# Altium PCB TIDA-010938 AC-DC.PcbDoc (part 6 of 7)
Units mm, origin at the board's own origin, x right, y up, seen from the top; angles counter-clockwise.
Board outline 275 x 170 mm, 4 copper layers (Top Layer, Layer 1, Layer 2, Bottom Layer), stack 1.787 mm thick; 711 components, 426 nets, 2196 pads, 1444 vias.
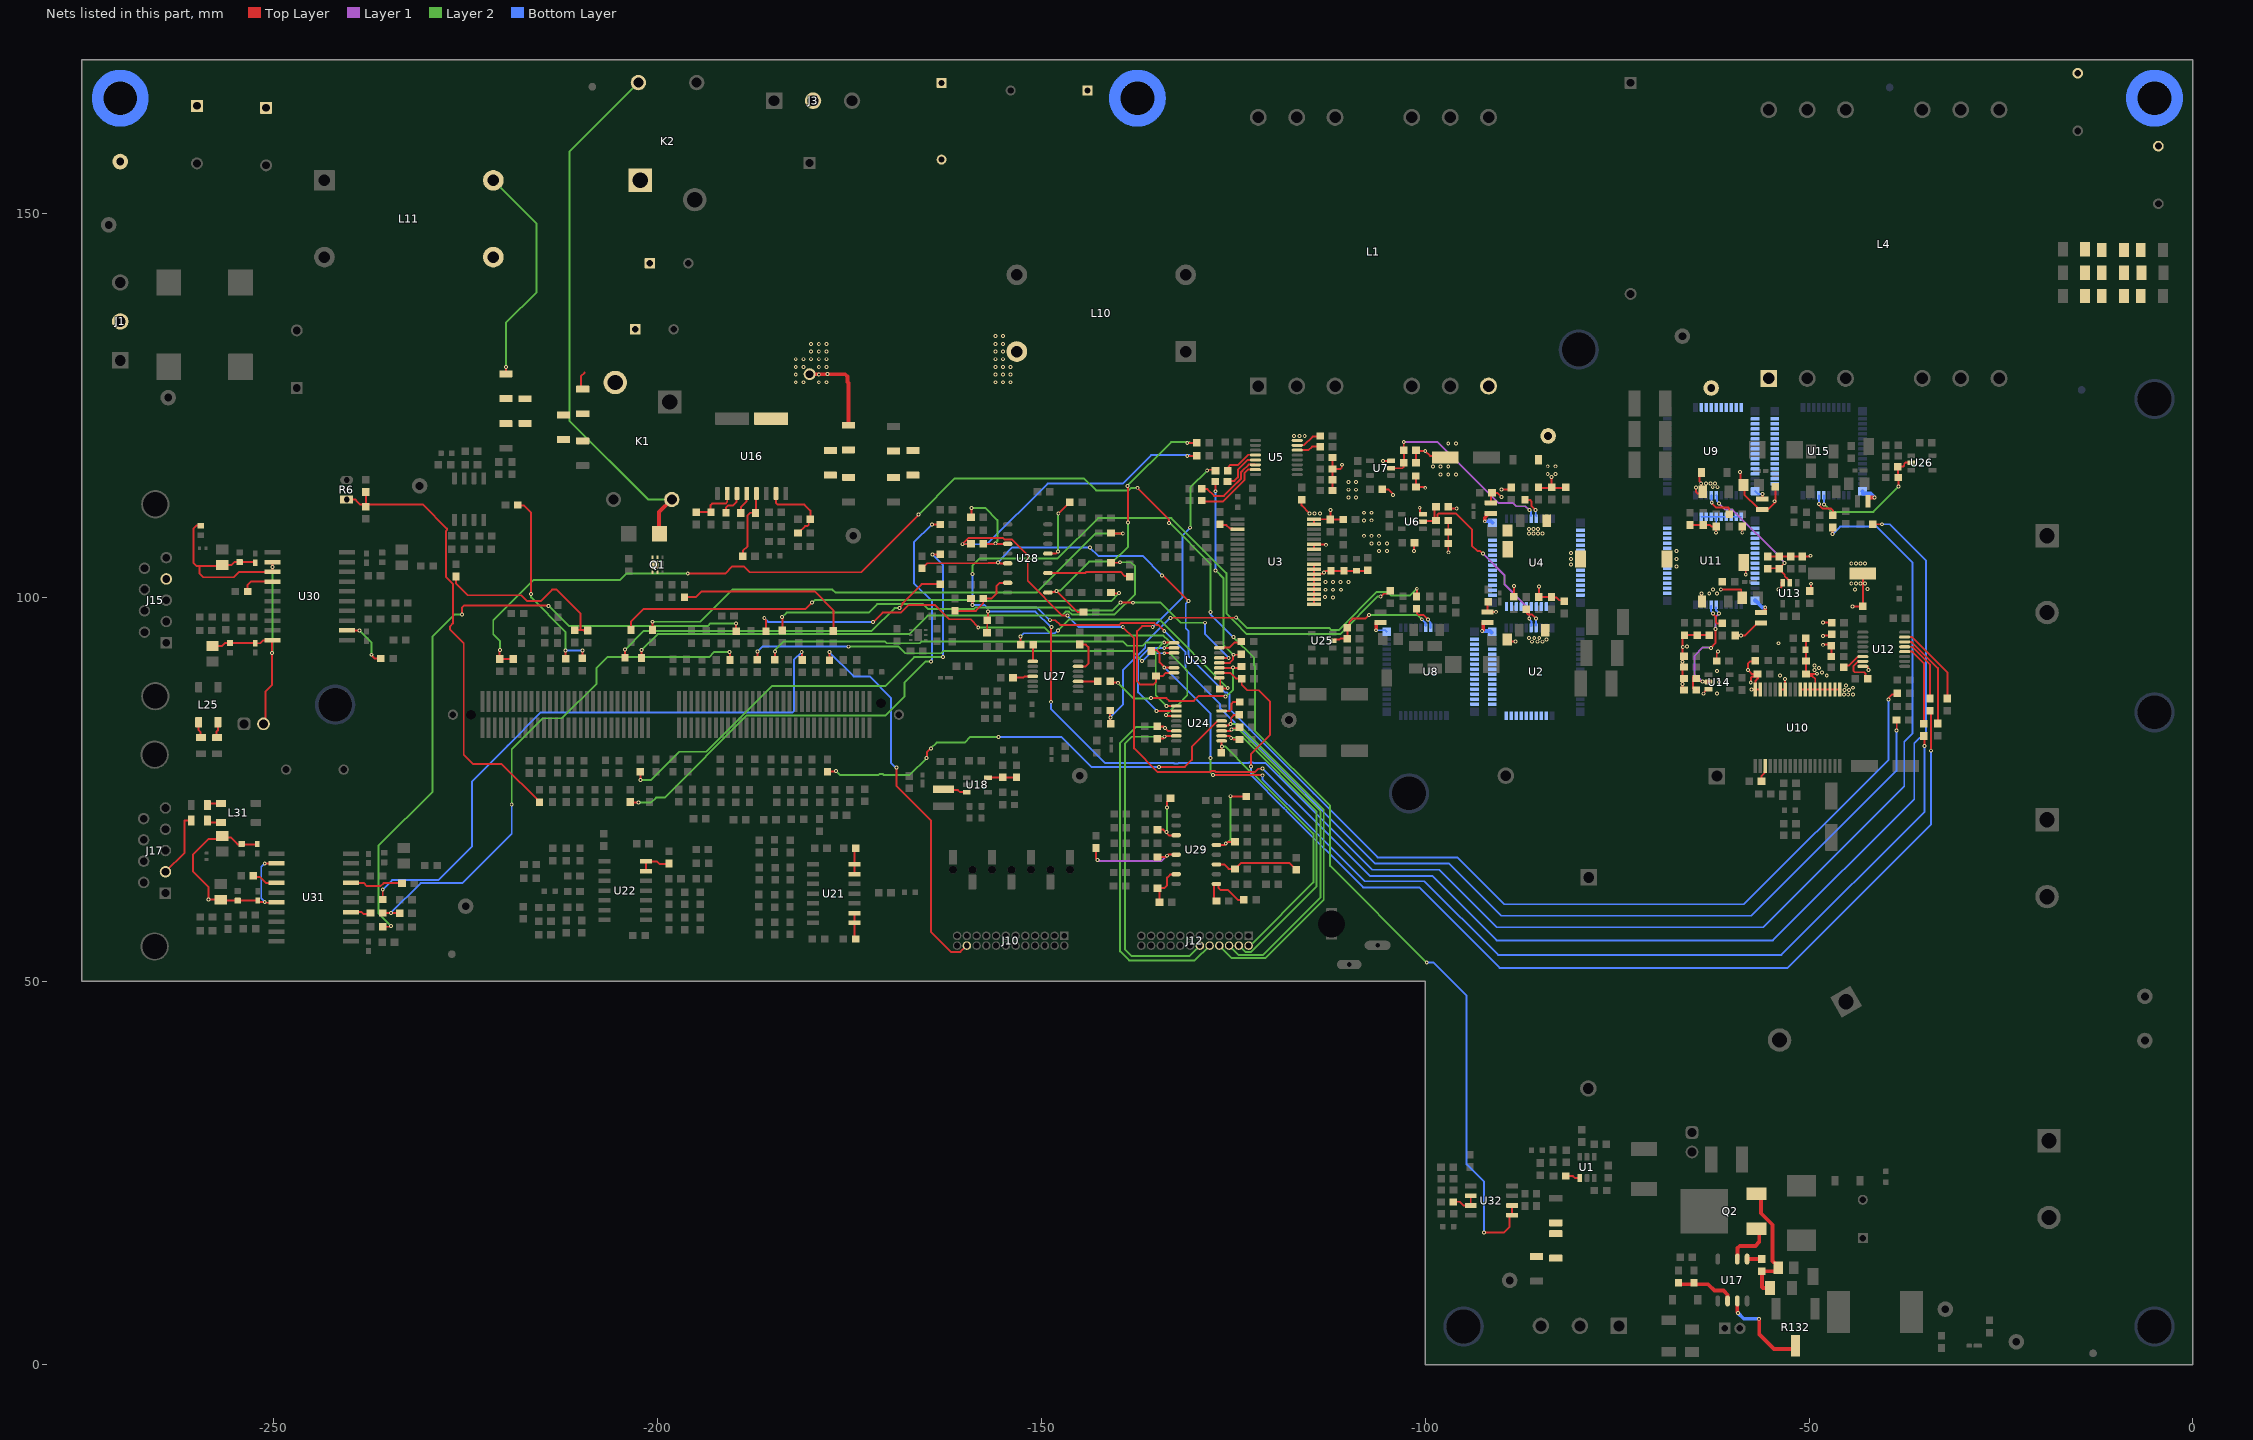
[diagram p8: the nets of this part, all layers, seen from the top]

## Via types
v1: diameter 0.508, hole 0.254, Top Layer to Bottom Layer, tented both sides, 1436 vias
v2: diameter 0.508, hole 0.254, Top Layer to Bottom Layer, 6 vias
v3: diameter 0.5, hole 0.2, Top Layer to Bottom Layer, 2 vias

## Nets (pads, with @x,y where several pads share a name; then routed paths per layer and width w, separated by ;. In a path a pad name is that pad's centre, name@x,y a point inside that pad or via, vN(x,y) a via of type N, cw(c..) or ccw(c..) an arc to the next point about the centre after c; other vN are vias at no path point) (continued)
NetJ17_2: J17.2 R321.2 | length 8.6
  Top Layer w0.25: J17.2@-264.105,64.23 -261.6,66.735 -261.6,70.9 R321.2@-260.75,70.9
NetL2_2: L2.2 U2.42 | length 3
  Top Layer w0.5: v1(-92.579,95.606) -92.579,95.608 -92.45,95.737 -92.45,96.65 -92.375,96.725 L2.2@-91.9,96.725
  Bottom Layer w0.5: v1(-92.579,95.606) -92.577,95.604 -91.571,95.604 U2.42@-91.375,95.408
NetL3_2: L3.2 U4.42 | length 2.7
  Top Layer w0.5: v1(-92.25,109.888) -92.248,109.89 -92.248,110.352 -92,110.6 -92,110.85 L3.2@-91.5,110.85
  Bottom Layer w0.5: v1(-92.25,109.888) -92.248,109.887 -91.412,109.887 U4.42@-91.225,109.7
NetL5_2: L5.2 U8.42 | length 3
  Top Layer w0.5: v1(-106.389,95.693) -106.389,95.696 -106.375,95.71 -106.375,96.65 -106.3,96.725 L5.2@-105.825,96.725
  Bottom Layer w0.25: v1(-106.389,95.693) -105.211,95.693 U8.42@-105.018,95.5
NetL6_2: L6.2 U9.42 | length 1.8
  Top Layer w0.25: L6.2@-56.1,112.775 -56.077,112.798 v1(-56.077,113.421)
  Bottom Layer w0.25: U9.42@-57.025,113.8 -56.648,113.423 -56.079,113.423 v1(-56.077,113.421)
NetL7_2: L7.2 U11.42 | length 2.9
  Top Layer w0.5: L7.2@-56.25,97.975 -55.784,97.975 -55.709,98.05 -55.709,98.645 v1(-55.708,98.646)
  Bottom Layer w0.5: U11.42@-57.025,99.55 -57,99.55 -56.098,98.648 v1(-55.708,98.646) v1(-55.708,98.646)
NetL9_2: L9.2 U15.42 | length 3
  Top Layer w0.5: L9.2@-42.325,112.5 -42.325,112.925 -42.25,113 v1(-41.5,113)
  Bottom Layer w0.5: U15.42@-43.025,113.8 U15.42@-43,113.8 ; U15.42@-43,113.5 -42,113.5 v1(-41.5,113)
NetL14_1: L14.1 U18.3 | length 2.9
  Top Layer w0.25: L14.1@-162.766,74.981 -162.66,74.875 -160.875,74.875 -160.599,74.599 -160.049,74.599 U18.3@-160,74.55
NetL25_3: L25.3 R316.1 | length 1.9
  Top Layer w0.25: L25.3@-259.775,83.725 -259.775,82.675 -259.525,82.425 R316.1@-259.525,81.95
NetL25_4: L25.4 R312.1 | length 1.9
  Top Layer w0.25: R312.1@-257.45,81.95 -257.475,81.975 -257.475,82.45 -257.275,82.65 L25.4@-257.275,83.725
NetL31_3: L31.3 R325.1 | length 1.9
  Top Layer w0.25: R325.1@-258.709,72.922 -258.507,73.125 -256.9,73.125 L31.3@-256.875,73.15
NetL31_4: L31.4 R321.1 | length 1.7
  Top Layer w0.25: R321.1@-258.65,70.9 -258.425,70.675 -257.125,70.675 L31.4@-257.1,70.7
NetQ2_1: Q2.1 U17.6 | length 5.9
  Top Layer w0.5: U17.6@-59.349,13.777 -59.33,13.796 -59.33,14.292 -59.303,14.319 -59.303,15.207 -59.01,15.5 -57,15.5 -56.5,16 -56.5,17.07 Q2.1@-56.35,17.22
NetQ2_3: Q2.3 R96.2 R97.1 R98.1 | length 16.4
  Top Layer w0.5: Q2.3@-56.85,22.28 -56.8,22.28 -56.25,21.73 -56.25,19.758 -54.75,18.258 -54.75,13.95 -54.748,13.948 -54.748,13.548 -54.233,13.033 R97.1@-54.233,12.117 ; R98.1@-55.1,9.75 -55.35,10 -56,10 -56.15,10.15 R96.2@-56.15,12.2 R97.1@-54.316,12.2
NetR2_1: R2.1 U1.1 | length 1.9
  Top Layer w0.25: R2.1@-81.625,24.625 -81.6,24.6 -80.775,24.6 -80.518,24.343 U1.1@-79.883,24.343
NetR8_1: R8.1 U5.7 | length 3.3
  Top Layer w0.25: U5.7@-116.675,119.788 -115.812,119.788 -114.675,120.925 R8.1@-113.8,120.925
NetR9_1: R9.1 U5.6 | length 3.1
  Top Layer w0.25: U5.6@-116.675,119.153 -115.222,119.153 -114.75,119.625 -113.925,119.625 R9.1@-113.85,119.55
NetR11_2: R11.2 U3.3 | length 2.1
  Top Layer w0.25: R11.2@-126.725,109.5 -126.625,109.4 -125.9,109.4 -125.45,108.95 -125.125,108.95 U3.3@-124.925,108.75
NetR18_1: R18.1 U12.7 | length 4.7
  Top Layer w0.25: U12.7@-43.637,91.61 -44.2,91.047 -44.2,90.371 -44.054,90.225 -42.8,90.225 -42.654,90.079 -42.654,89.725 -42.579,89.65 R18.1@-42.075,89.65 ; U12.7@-43.562,91.635 -43.256,91.635 U12.7@-43,91.635 ; U12.7@-43.256,91.606 U12.7@-43.225,91.575
NetR19_1: R19.1 U12.6 | length 2.6
  Top Layer w0.25: R19.1@-45.5,90.875 -45.265,91.11 -44.771,91.11 U12.6@-43.657,92.225 ; U12.6@-43.582,92.25 U12.6@-43.375,92.25 ; U12.6@-43.18,92.27 U12.6@-43.175,92.275
NetR21_2: R21.2 R23.1
NetR23_2: R23.2 R36.1
NetR24_2: R24.2 U5.12 | length 4.1
  Top Layer w0.25: R24.2@-125.725,116.475 -125.65,116.55 -125.65,116.95 -125.375,117.225 -124.381,117.225 -123.056,118.55 U5.12@-122.75,118.55 ; R24.2@-125.55,116.5 R24.2@-125.525,116.475 ; U5.12@-122.154,118.489 U5.12@-122.125,118.518
NetR26_2: R26.2 U5.13 | length 5.2
  Top Layer w0.25: R26.2@-125.6,115.15 -124.85,115.15 -124.4,115.6 -124.4,116.59 -123.108,117.883 U5.13@-122.125,117.883
NetR28_2: R28.2 U5.14 | length 9.6
  Top Layer w0.25: R28.2@-129.1,114.125 -129.046,114.071 -128.371,114.071 -127.5,113.2 -126.234,113.2 -125.109,114.325 -124,115.434 -124,115.5 -123.975,115.525 -123.975,116.303 -123.828,116.45 -123.825,116.45 -123,117.275 -122.152,117.275 U5.14@-122.125,117.248
NetR31_2: R31.2 U5.15 | length 8.8
  Top Layer w0.25: R31.2@-128.7,112.475 -126.325,112.475 -123.567,115.233 -123.567,116.142 -123.097,116.613 U5.15@-122.125,116.613
NetR37_2: R37.2 U8.49 | length 3.5
  Top Layer w0.25: R37.2@-101.15,98.5 -101.05,98.4 -101.05,97.85 -100.854,97.654 -100.204,97.654 -99.734,97.184 -99.716,97.184 v1@-99.7,97.2
  Bottom Layer w0.25: v1@-99.575,97.05 -99.601,97.024 -99.601,96.981 -99.327,96.707 -99.327,96.019 U8.49@-99.308,96
  other v1: -99.65,97.1
NetR39_1: R39.1 U27.3 | length 2.7
  Top Layer w0.25: U27.3@-145.219,89.033 -142.558,89.033 R39.1@-142.5,88.975
NetR47_2: R47.2 U10.3 | length 1.7
  Top Layer w0.25: R47.2@-56.2,76.025 -56.2,76.69 -55.825,77.065 -55.825,77.275 U10.3@-55.65,77.45
NetR50_1: R50.1 U30.2 | length 6.9
  Top Layer w0.25: U30.2@-240.456,95.682 -240.45,95.676 -238.852,95.676 v1(-238.846,95.67) ; v1(-237.25,92.5) -237.25,92.43 -237.021,92.201 -237.021,92.158 -236.864,92 R50.1@-236.05,92
  Layer 2 w0.25: v1(-238.846,95.67) -237.25,94.074 v1(-237.25,92.5)
NetR58_2: R58.2 U12.12 | length 11.2
  Top Layer w0.25: U12.12@-37.55,92.905 -36.53,92.905 -35.05,91.425 -35.05,83.7 R58.2@-35.275,83.475
NetR61_2: R61.2 U12.13 | length 8.6
  Top Layer w0.25: U12.13@-37.55,93.54 -36.556,93.54 -34.25,91.234 R61.2@-34.25,86.85
NetR63_2: R63.2 U12.14 | length 12.5
  Top Layer w0.25: U12.14@-37.55,94.175 -37.521,94.146 -36.596,94.146 -33.225,90.775 R63.2@-33.225,84
NetR65_2: R65.2 U12.15 | length 10.7
  Top Layer w0.25: U12.15@-37.55,94.81 -36.56,94.81 -31.975,90.225 R65.2@-31.975,86.975
NetR68_1: R68.1 U27.6 | length 4.4
  Top Layer w0.25: R68.1@-145.014,93.829 -144.204,93.829 -143.875,93.5 -143.875,91.35 -144.25,90.975 U27.6@-144.65,90.975
NetR71_2: R71.2 U15.49 | length 4.2
  Top Layer w0.25: v1(-48.725,112.125) -48.725,112.055 -48.579,111.909 -48.579,111.881 -48.269,111.571 -47.146,111.571 -46.9,111.325 -46.9,110.725 R71.2@-46.725,110.55
  Bottom Layer w0.152: v1@-48.73,112.13 v1(-48.725,112.125)
  Bottom Layer w0.25: U15.49@-48.735,113.275 -48.73,113.27 v1@-48.73,112.195
NetR73_1: R73.1 U27.8 | length 2.2
  Top Layer w0.25: R73.1@-151.075,93.8 -151.119,93.756 -151.119,91.725 -151.094,91.7 U27.8@-151.05,91.7
NetR77_1: R77.1 R79.1 R80.1 R185.2 R235.2 R290.2
NetR83_1: R83.1 U16.6 | length 2.8
  Top Layer w0.25: R83.1@-189.15,111.025 -189.15,111.725 -188.4,112.475 -188.4,113.501 U16.6@-188.385,113.516
NetR84_2: R84.2 R88.1 U16.4 | length 6.1
  Top Layer w0.25: R84.2@-194.978,111.079 -193.304,111.079 R88.1@-193.125,110.9 ; R88.1@-193.1,111.225 -193.1,112 -192.9,112.2 -191.15,112.2 -190.925,112.425 U16.4@-190.925,113.516
NetR85_2: R85.2 R87.1 U16.7 | length 8.9
  Top Layer w0.25: R85.2@-188.875,105.625 -188.875,106.05 -188.275,106.65 -188.275,110.675 -187.95,111 -187.275,111 R87.1@-187.25,110.975 ; R87.1@-187.2,111.125 -187.2,113.431 U16.7@-187.115,113.516
NetR86_2: R86.2 U16.5 | length 3.1
  Top Layer w0.25: R86.2@-191.075,111.425 -191.075,111.709 -190.855,111.93 -190.22,111.93 -189.7,112.45 -189.7,113.471 U16.5@-189.655,113.516
NetR91_2: R91.2 R92.2 U16.9 | length 9.8
  Top Layer w0.25: U16.9@-184.575,113.516 -184.575,112.3 -184.325,112.05 -180.875,112.05 -180.1,111.275 ; R91.2@-181.696,108.373 -181.671,108.373 -180.794,109.25 -180.5,109.25 -180.303,109.447 -180.303,109.952 -180.1,110.155 -180.1,111.25
NetR93_1: R93.1 R95.2 U17.2 | length 7.8
  Top Layer w0.5: R93.1@-67,10.7 -66.8,10.5 -65,10.5 -63.169,10.5 -62.338,9.669 -61.167,9.669 -60.638,9.14 -60.638,8.346 U17.2@-60.619,8.327
NetR96_1: R96.1 U17.5 | length 1.9
  Top Layer w0.5: U17.5@-58.079,13.777 -58.067,13.788 -56.162,13.788 R96.1@-56.15,13.8
NetR99_2: R99.2 U30.14 | length 4.3
  Top Layer w0.25: R99.2@-253.4,100.75 -253.4,101.6 -252.968,102.032 U30.14@-250.156,102.032
NetR103_2: R103.2 R106.1 U18.5 | length 3.5
  Top Layer w0.25: U18.5@-156.958,76.499 -153.549,76.499 R103.2@-153.475,76.425
NetR111_2: R111.2 R112.1
NetR112_2: R112.2 R113.1
NetR116_2: R116.2 R117.1
NetR117_2: R117.2 R118.1
NetR122_2: R122.2 R123.1
NetR123_2: R123.2 R124.1
NetR125_1: R125.1 U31.7 | length 7
  Top Layer w0.25: U31.7@-239.92,62.789 -238.289,62.789 -237.854,62.354 -236.095,62.354 -235.698,62.75 R125.1@-233.3,62.75
NetR126_2: R126.2 U31.14 | length 3.4
  Top Layer w0.25: R126.2@-252.648,63.698 -252.502,63.552 -251.802,63.552 -251.039,62.789 U31.14@-249.62,62.789
NetR127_2: R127.2 R128.1
NetR128_2: R128.2 R129.1
NetR132_2: R132.2 U17.3 | length 12.2
  Top Layer w0.5: U17.3@-59.349,8.327 -59.349,6.851 -59.25,6.752 v1(-59.25,6.75) ; v1(-56.5,6) -56.5,4 -54.585,2.085 R132.2@-51.75,2.085
  Bottom Layer w0.5: v1(-59.25,6.75) -58.5,6 v1(-56.5,6)
NetR134_1: R134.1 U32.6 U32.7 | length 3.1
  Top Layer w0.25: R134.1@-96.35,21.225 -96.325,21.25 -95.5,21.25 -95.025,20.775 -94.65,20.775 U32.7@-94.625,20.8 ; U32.7@-94.075,20.925 U32.6@-94.075,22.035
NetR140_1: R140.1 U21.1 U21.2 | length 3.5
  Top Layer w0.25: U21.2@-174.325,58.825 U21.2@-174.347,58.847 U21.1@-174.347,57.577 -174.347,55.62 R140.1@-174.201,55.474
NetR150_1: R150.1 U21.6 U21.7 | length 3.4
  Top Layer w0.25: U21.6@-174.347,63.927 U21.7@-174.347,65.197 R150.1@-174.347,67.278
NetR170_1: R170.1 U22.13 U22.14 | length 4.6
  Top Layer w0.25: U22.13@-201.504,64.315 U22.14@-201.504,65.554 ; U22.14@-201.504,65.585 -200.11,65.585 -199.775,65.25 -198.375,65.25 R170.1@-198.3,65.175
NetR177_2: R177.2 U23.7 | length 3
  Top Layer w0.25: U23.7@-126.825,93.4 -126.787,93.438 U23.7@-126.2,93.438 ; U23.7@-126.2,93.4 -126.162,93.438 -125.512,93.438 -124.875,94.075 -124.3,94.075 R177.2@-124.175,94.2
NetR185_1: R185.1 R235.1 R290.1 R291.2 R326.2 R327.2
NetR202_2: R202.2 U24.7 | length 3.1
  Top Layer w0.25: U24.7@-126.525,85.175 -125.475,85.175 -125.225,85.425 -125.225,86.15 -125.025,86.35 R202.2@-124.35,86.35
NetR239_1: R239.1 U27.11 | length 2.6
  Top Layer w0.25: R239.1@-153.482,89.75 R239.1@-153.709,89.523 -152.352,89.523 -152.2,89.675 -151.575,89.675 U27.11@-151.525,89.725
NetR240_2: R240.2 R286.1 U29.13 | length 11.1
  Top Layer w0.25: U29.13@-127.2,67.725 -126.125,67.725 -125.75,68.1 -124.875,68.1 R286.1@-124.85,68.125 ; v1@-125.4,74.05 -125.375,74.025 R240.2@-123.325,74.025
  Layer 2 w0.25: v1@-126.011,67.839 -125.35,68.5 v1(-125.35,74.075)
  other v1: -125.986,67.914
NetR241_2: R241.2 U28.13 | length 8.6
  Top Layer w0.25: U28.13@-149.15,105.685 -148.15,105.685 -147.885,105.95 v1(-147.825,105.95) ; v1@-147.87,110.825 -147.85,110.825 -146.675,112 -146.675,112.025 -146.325,112.375 R241.2@-146.3,112.375
  Layer 2 w0.25: v1(-147.825,105.95) -147.813,105.962 -147.813,110.888 v1(-147.8,110.9)
NetR242_2: R242.2 R284.1 U29.11 | length 11.3
  Top Layer w0.25: U29.11@-127.2,65.185 -126.21,65.185 -125.619,64.594 R284.1@-124.8,64.594 ; R284.1@-124.783,64.602 -124.758,64.602 -124.008,65.352 -117.659,65.352 -117.157,64.85 -117.15,64.85 -116.8,64.5 R242.2@-116.8,64.475
NetR243_2: R243.2 U28.11 | length 11
  Top Layer w0.25: U28.11@-149.15,103.145 -144.316,103.145 -144.167,103.294 -139.694,103.294 -139.179,102.778 -138.603,102.778 R243.2@-138.475,102.65
NetR244_2: R244.2 R279.1 U29.9 | length 7.1
  Top Layer w0.25: R279.1@-127.2,60.425 -127.5,60.725 -127.5,62.506 -127.361,62.645 -127.07,62.645 -126.931,62.506 -126.931,62.131 -126.65,61.85 -125.661,61.85 -124.356,60.544 -123.819,60.544 R244.2@-123.75,60.475
NetR246_2: R246.2 R272.1 U29.7 | length 5.6
  Top Layer w0.25: R246.2@-134.625,60.25 -134.625,61.787 -134.9,62.062 R272.1@-134.867,62.095 -133.98,62.095 -133.625,62.45 -133.625,63.475 -133.243,63.857 -132.618,63.857 U29.7@-132.575,63.9
NetR247_2: R247.2 R269.1 U28.7 | length 9.1
  Top Layer w0.25: R247.2@-161.25,98.225 -158.529,98.225 -157.575,99.179 R269.1@-157.575,99.835 -156.465,99.835 -155.85,100.45 -155.85,101.45 -155.475,101.825 -154.825,101.825 U28.7@-154.7,101.95
NetR248_2: R248.2 R264.1 U29.5 | length 13.2
  Top Layer w0.25: R248.2@-142.9,67.325 -142.9,66.02 -142.7,65.82 v1(-142.7,65.75) ; R264.1@-134.867,66.159 -133.791,66.159 -133.45,66.5 -132.925,66.5 U29.5@-132.85,66.575
  Layer 1 w0.25: v1(-142.7,65.75) -142.651,65.701 -142.479,65.701 -142.425,65.646 -134.329,65.646 v1(-133.65,66.325)
NetR250_2: R250.2 R259.1 U29.3 | length 7.6
  Top Layer w0.25: R259.1@-134.867,69.715 -134.115,69.715 -133.35,68.95 U29.3@-132.425,68.95 ; v1@-133.65,72.525 -133.65,73.35 -133.55,73.45 -133.55,73.475 -133.2,73.825 R250.2@-133.175,73.825
  Layer 2 w0.25: v1@-133.733,69.333 -133.625,69.44 v1(-133.625,72.6)
  other v1: -133.708,69.408
NetR251_2: R251.2 R257.1 U28.3 | length 11.5
  Top Layer w0.25: R251.2@-159.175,110.425 -159.125,110.475 v1@-159.125,111.55 ; R257.1@-157.575,106.947 -154.408,106.947 U28.3@-154.4,106.955
  Layer 2 w0.25: v1(-159.1,111.625) -157.3,111.625 -155.725,110.05 -155.725,107.333 -155.967,107.092 v1(-155.967,107.022)
NetR319_2: R319.2 U31.4 | length 2.5
  Top Layer w0.25: U31.4@-239.92,58.979 -238.554,58.979 -238.3,58.725 -237.525,58.725 R319.2@-237.5,58.7
O\C\_S1: C246.2 R328.2 U2.48 U6.2 | length 26
  Top Layer w0.25: U6.2@-100.3,109.85 -100.25,109.9 -98.7,109.9 C246.2@-98.6,110 ; R328.2@-98.7,111.8 R328.2@-98.675,111.825 ; R328.2@-98.6,111.8 -98.8,111.6 -98.8,110.2 C246.2@-98.6,110 ; v1(-92.488,105.7) -92.558,105.7 -92.885,106.027 -93.227,106.027 -93.925,106.725 -93.925,108.825 -95.975,110.875 -98.279,110.875 -98.425,110.729 -98.425,110.175 C246.2@-98.6,110
  Layer 1 w0.25: v1(-92.488,105.7) -89.675,102.887 -89.675,101.675 -86.45,98.45 v1(-86.45,97.2)
  Bottom Layer w0.25: v1(-86.45,97.2) -86.45,97.13 -86.15,96.83 -86.15,96.3 U2.48@-86.2,96.25
O\C\_S2_init: C255.2 R337.2 U8.48 U25.2 | length 15.4
  Top Layer w0.25: U25.2@-112.051,94.329 -111.895,94.485 -111.176,94.485 -111.056,94.604 C255.2@-110.162,94.604 -110.15,94.616 R337.2@-110.15,96.025 -109.9,96.275 -109.9,96.754 -109.451,97.202 -107.798,97.202 v1(-107.3,97.7)
  Layer 2 w0.25: v1(-107.3,97.7) -101.025,97.7 v1(-100.45,97.125)
  Bottom Layer w0.25: v1(-100.45,97.125) -100.423,97.125 -99.991,96.693 -99.991,96.366 U8.48@-99.925,96.3
O\C\_S3: C250.2 R332.2 U9.48 U13.2 | length 17.5
  Top Layer w0.25: R332.2@-55,103.7 -54.925,103.775 C250.2@-53.9,103.775 ; C250.2@-53.9,103.7 -53.9,103.675 -53.862,103.638 -53.167,102.942 -53.167,102.751 -52.875,102.459 -52.875,102.45 -52.65,102.225 U13.2@-52.4,102.225 ; C250.2@-53.85,103.65 -53.55,103.95 -53.55,104.075 -53.176,104.449 v1(-53.176,104.47)
  Layer 1 w0.25: v1(-61.75,112.225) -60.925,111.4 -60,111.4 -53.656,105.056 -53.656,104.95 v1(-53.176,104.47)
  Bottom Layer w0.25: U9.48@-62.085,113.275 -61.985,113.175 -61.985,112.53 -61.75,112.295 v1(-61.75,112.225)
O\C\_S4_init: C256.2 R338.2 U15.48 U26.2 | length 17
  Top Layer w0.25: C256.2@-38.429,117.008 C256.2@-38.4,117.008 ; v1@-38.4,114.45 -38.35,114.5 -38.35,115.55 R338.2@-38.4,115.6 C256.2@-38.4,117.008 ; U26.2@-36.95,117.525 -37.454,117.525 -37.6,117.379 -37.6,117.154 -37.746,117.008 C256.2@-38.4,117.008
  Layer 2 w0.25: v1(-48.05,112.1) -47.071,111.121 -41.629,111.121 v1@-38.375,114.375
  Bottom Layer w0.152: v1@-48.068,112.118 v1(-48.05,112.1)
  Bottom Layer w0.25: U15.48@-48.085,113.275 -48.068,113.258 -48.068,112.157 v1@-48.075,112.15
  other v1: -38.35,114.4
O\C\_S5: C248.2 R330.2 U4.48 U7.2 | length 25.8
  Top Layer w0.25: U7.2@-104.425,116.825 U7.2@-104.45,116.8 -102.971,116.8 -102.825,116.946 C248.2@-102.825,117.525 ; v1(-102.8,120.225) R330.2@-102.8,119.125 -102.75,119.075 C248.2@-102.75,117.65
  Layer 1 w0.25: v1(-102.8,120.225) -98.425,120.225 -90.45,112.25 -88.561,112.25 -88.161,111.85 -86.945,111.85 -86.47,111.375 v1(-86.4,111.375)
  Bottom Layer w0.25: v1(-86.4,111.375) -86.4,111.305 -86.2,111.105 U4.48@-86.2,110.6
O\C\_S6: C89.2 R34.2 U11.48 U14.2 | length 15.5
  Top Layer w0.25: R34.2@-65.1,88.1 C89.2@-65.1,89.6 ; C89.2@-64.9,89.4 -64.55,89.05 -64.02,89.05 -63.97,89 v1(-63.9,89) -63.875,88.975 -63.375,88.975 U14.2@-63.3,88.9 ; v1@-62.775,93.425 -62.205,93.995 v1(-62.205,95.879)
  Layer 1 w0.25: v1(-63.9,89) -64.383,89.483 -64.483,89.483 -64.9,89.9 -64.9,92.375 -63.825,93.45 v1@-62.853,93.45 ; v1(-62.205,95.879) -62.205,97.395 v1(-61.75,97.85)
  Bottom Layer w0.25: U11.48@-62.125,98.65 -62.1,98.625 -62.1,98.27 -61.75,97.92 v1(-61.75,97.85)
  other v1: -62.8,93.4
PE: J1.2 MP1.1 R78.1 R81.1 TP14.1
PE2: C102.2 C106.1 J3.2 MP2.1
PE3: C243.1 C244.2 MP9.1
PWM_S1: R190.1 R260.1 | length 68.7
  Top Layer w0.25: R190.1@-203.5,73.3 -203.475,73.275 v1(-202.5,73.275) ; v1@-164.3,109.4 -164.237,109.463 R260.1@-163.185,109.463
  Layer 2 w0.25: v1(-202.5,73.275) -200.823,73.275 -200.198,73.9 -199.073,73.9 -188.373,84.6 -170.3,84.6 -167.817,87.083 -167.817,88.916 -165.133,91.6 v1(-164.4,91.6)
  Bottom Layer w0.25: v1(-164.4,91.6) -164.4,91.67 -164.25,91.82 -164.25,99.467 -166.6,101.817 -166.6,107.125 v1@-164.3,109.425
  other v1: -164.275,109.45
PWM_S1_Buff: R22.1 R69.1 R257.2 | length 241.9
  Top Layer w0.25: R257.2@-159.175,106.947 -159.222,106.9 v1(-160.3,106.9) -159.503,107.697 -155,107.697 -154.823,107.52 -153.838,107.52 -151.783,105.466 -151.783,102.11 -147.273,97.6 v1(-146.625,97.6) ; v1(-139.4,96.1) -137.929,94.629 -137.929,80.29 -134.889,77.25 -127.998,77.25 -127.869,77.379 -127.431,77.379 -127.302,77.25 -122.154,77.25 -121.753,77.651 -121.249,77.651 v1(-121.2,77.7) ; v1(-131,118.4) -129.775,118.4 R22.1@-129.75,118.425 ; R69.1@-41.7,109.5 v1(-40.5,109.5)
  Bottom Layer w0.25: v1(-160.3,106.9) -157.1,106.9 -149.2,114.8 -139.4,114.8 -135.7,118.5 -130.7,118.5 ; v1(-146.625,97.6) -145.125,96.1 v1(-139.4,96.1) ; v1(-121.2,77.7) -107.2,63.7 -99.1,63.7 -90.7,55.3 -54.7,55.3 -36.3,73.7 -36.3,80.95 -34.75,82.5 -34.75,104.75 -39.5,109.5 v1(-40.5,109.5)
PWM_S2: R192.1 R265.1 | length 62.1
  Top Layer w0.25: R192.1@-202.244,77.251 -202.2,77.207 v1(-202.2,76.2) ; v1@-164.175,105.58 R265.1@-163.185,105.58
  Layer 2 w0.25: v1(-202.2,76.2) -200.823,76.2 -197.152,79.871 -193.668,79.871 -185.118,88.421 -170.356,88.421 -166.577,92.2 v1(-162.8,92.2)
  Bottom Layer w0.25: v1@-164.2,105.6 -164.2,105.575 v1(-164.175,105.55) -162.8,104.175 v1(-162.8,92.2)
PWM_S2_Buff: R35.1 R56.1 R269.2 | length 228.2
  Top Layer w0.25: R269.2@-159.175,99.835 -159,99.66 v1(-159,99) ; v1(-148.9,97) -148.166,97 -147.566,96.4 -139.848,96.4 -139.619,96.629 -135.281,96.629 -135.052,96.4 -134.8,96.4 v1(-134,95.6) ; v1(-105.8,100.1) -105.73,100.1 -105.38,100.45 -104.925,100.45 -104.575,100.8 R35.1@-104.575,100.825 ; R56.1@-38.6,84 -38.575,83.975 v1@-38.575,82.6
  Layer 2 w0.25: v1(-159,103) -159,104.075 -158.025,105.05 -147.875,105.05 -142.621,110.304 -133.054,110.304 -125.9,103.15 -125.9,97.877 -124.844,96.821 -123.223,95.2 -111.1,95.2 -106.2,100.1 v1(-105.8,100.1)
  Bottom Layer w0.25: v1(-159,103) v1(-159,99) -157.473,99 -157.148,98.675 -150.575,98.675 v1(-148.9,97) ; v1(-134,95.6) -131.225,92.825 -131.225,90.577 -126.719,86.071 -126.719,85.519 -125.229,84.029 -125.156,84.029 -124.846,83.719 -124.846,83.646 -106.5,65.3 -96.9,65.3 -90.1,58.5 -57.5,58.5 -38.625,77.375 v1(-38.625,82.65)
PWM_S3: R194.1 R268.1 | length 45.7
  Top Layer w0.25: v1(-204.225,93.175) -204.225,92.225 R194.1@-204.175,92.175 ; v1(-168.475,98.574) -168.475,98.643 -168.068,99.051 -168.068,99.232 -165.603,101.697 R268.1@-163.185,101.697
  Layer 2 w0.25: v1(-204.225,93.175) -201.8,95.6 -172.1,95.6 -169.126,98.574 v1(-168.475,98.574)
PWM_S4: R196.1 R273.1 | length 67.3
  Top Layer w0.25: R196.1@-203.425,95.775 -203.45,95.8 -203.45,96.85 -201.854,98.446 -180.754,98.446 v1(-179.9,99.3) ; R273.1@-140.943,100.602 -140.841,100.5 v1@-139.9,100.5
  Layer 2 w0.25: v1(-179.9,99.3) -179.83,99.3 -179.506,99.624 -158.876,99.624 -158.754,99.503 -140.922,99.503 v1@-139.925,100.5
  other v1: -139.875,100.55
PWM_S5: R191.2 R276.1 | length 75.4
  Top Layer w0.25: v1(-202.075,93.125) -202.075,92.275 R191.2@-202.025,92.225 ; R276.1@-140.943,104.485 -139.815,104.485 v1@-139.8,104.5
  Layer 2 w0.25: v1(-202.075,93.125) -200,95.2 -167.229,95.2 -164.833,97.596 -147.377,97.596 -146.844,98.129 -146.406,98.129 -146.027,97.75 -140.45,97.75 -137.8,100.4 -137.8,104 -138.35,104.55 -139.656,104.55 -139.7,104.594 v1@-139.7,104.6
  other v1: -139.775,104.55
PWM_S5_Buff: R20.1 R245.2 U28.9 | length 37.4
  Top Layer w0.25: U28.9@-149.051,100.506 U28.9@-149.15,100.605 -149.093,100.662 -148.254,100.662 -148.107,100.81 v1(-148.037,100.81) -145.302,98.075 R245.2@-144.525,98.075 ; v1(-138.8,114.5) -138.751,114.451 -138.751,114.306 -138.7,114.255 v1@-138.7,109.9 ; v1(-131,120.1) -129.775,120.1 R20.1@-129.75,120.125
  Layer 2 w0.25: v1(-148.037,100.81) -147.988,100.859 -147.56,100.859 -143.794,104.625 -140.675,104.625 -138.7,106.6 v1@-138.7,109.9 ; v1(-138.8,114.5) -133.1,120.2 -130.7,120.2
  other v1: -138.725,109.75
PWM_S6: R193.2 R281.1 | length 68.9
  Top Layer w0.25: v1(-200.65,96.8) -200.65,95.9 R193.2@-200.6,95.85 ; R281.1@-140.943,108.368 -140.875,108.3 v1(-139.4,108.3)
  Layer 2 w0.25: v1(-200.65,96.8) -194.448,96.8 -190.248,101 -177.22,101 -176.84,100.62 -150.582,100.62 -142.902,108.3 v1(-139.4,108.3)
PWM_S6_Buff: R54.1 R249.2 U28.5 | length 170.2
  Top Layer w0.25: R249.2@-165.55,103.75 -165.55,103.775 -165.2,104.125 -165.175,104.125 -164.881,104.419 -156.911,104.419 -156.858,104.472 -155.683,104.472 v2@-155.645,104.51 ; v2@-155.633,104.613 -155.566,104.613 -155.368,104.415 -154.765,104.415 U28.5@-154.75,104.4 ; v1(-134.275,102.85) -134.213,102.85 -130.888,99.525 v1(-130.825,99.525) ; v1(-39.65,86.65) -39.581,86.719 -39.581,86.965 -39.229,87.317 -38.683,87.317 R54.1@-38.5,87.5
  Bottom Layer w0.25: v2(-155.633,104.521) -155.146,105.008 -155.146,105.1 -153.768,106.479 -145.934,106.479 -145.905,106.45 v1(-143.675,106.45) -142.6,105.375 -136.8,105.375 v1@-134.3,102.875 ; v1(-130.825,99.525) -131.2,99.15 -131.2,95.925 -130.825,95.55 -130.825,92.325 -126.079,87.579 -125.806,87.579 -125.496,87.269 -125.496,85.396 -114.553,74.453 -106.2,66.1 -95.8,66.1 -89.7,60 -58.5,60 -39.65,78.85 v1(-39.65,86.65)
RS485_D: R211.2 R323.1 | length 86.2
  Top Layer w0.25: R323.1@-235.804,57.074 -234.826,57.074 v1@-234.8,57.1 ; v1(-225.5,97.75) -225.5,98.63 -225.23,98.9 v1@-214.2,98.9 ; v1(-189.775,96.575) -189.758,96.558 R211.2@-189.758,95.576
  Layer 2 w0.25: v1(-234.734,57.186) -236.329,58.782 -236.329,67.657 -229.3,74.686 -229.3,94.9 -226.45,97.75 v1(-225.5,97.75) ; v1@-214.158,98.858 -211.571,96.271 -193.431,96.271 -193.127,96.575 v1(-189.775,96.575)
  other v1: -214.198,98.874
RS485_DE_R\E\: R228.2 R320.1 | length 78.6
  Top Layer w0.25: R320.1@-235.804,60.63 -235.8,60.634 v1(-235.8,61.9) ; v1@-181.2,92.8 -181.162,92.762 R228.2@-181.162,91.826
  Bottom Layer w0.25: v1(-235.8,61.9) -235.8,61.92 -234.574,63.146 -228.554,63.146 -224.152,67.548 -224.152,76 -219.526,80.626 -219.526,80.674 -215.2,85 -182.396,85 -182.25,85.146 -182.25,91.825 v1(-181.225,92.85)
RS485_R: C232.2 R209.2 R319.1 | length 68.8
  Top Layer w0.25: R319.1@-235.804,58.852 -233.752,58.852 C232.2@-233.7,58.8 ; v1@-190.6,92.7 -190.56,92.66 R209.2@-190.56,91.826
  Layer 2 w0.25: v1(-219,73) -219,80.198 -214.971,84.227 -212.475,84.227 -207.946,88.756 -207.946,90.804 -206.546,92.204 -193.296,92.204 -192.65,92.85 v1(-190.625,92.85)
  Bottom Layer w0.25: v1(-234.734,58.886) -230.874,62.746 -225.454,62.746 -219,69.2 v1(-219,73)
RY_DCPreCharge: J10.22 R234.2 | length 50.4
  Top Layer w0.25: R234.2@-177.606,91.788 v1@-177.606,92.85 ; v1(-168.9,77.8) -168.9,75.436 -164.4,70.936 -164.4,56.4 -161.785,53.785 -160.55,53.785 J10.22@-159.715,54.62
  Bottom Layer w0.25: v1@-177.7,92.9 -177.675,92.9 v1(-177.625,92.85) -174.463,89.688 -172.388,89.688 -169.6,86.9 -169.6,78.453 -168.947,77.8 v1(-168.9,77.8)
RY_PreCharge: R89.1 R236.2 | length 23.1
  Top Layer w0.25: R89.1@-196.5,100 -195,100 -194.25,100.75 -179.55,100.75 -177.1,98.3 R236.2@-177.1,95.925
SN_Relays_PreCharge: D13.2 K1.2 K2.2 Q1.1 Q1.2 Q1.5 Q1.6 Q1.8 | length 71
  Top Layer w0.5: D13.2@-199.8,108.1 -199.8,111.076 K1.2@-198.15,112.726
  Layer 2 w0.25: K2.2@-202.5,167.03 -211.5,158.03 -211.5,123 -201.226,112.726 K1.2@-198.15,112.726
  Bottom Layer w0.5: K1.2@-198.3,112.9 K1.2@-197.976,112.9
SW_1: C11.2 C12.2 C13.1 C14.1 C15.2 C16.1 C17.1 C19.1 C20.2 C21.2 C24.2 C25.1 C26.1 C27.1 C28.2 C32.1 C33.1 C34.1 C35.1 C39.2 C40.2 C43.2 C47.2 C245.1 C246.1 C247.1 C248.1 D2.2 L1.6 L2.1 L3.1 R10.1 R15.2 R17.1 R30.1 R42.1 R237.1 R328.1 R329.1 R330.1 TP4.1 TP17.1 U2.18 U2.19 U2.20 U2.21 U2.22 U2.23 U2.24 U2.25 U2.26 U2.28 U2.29 U2.30 U2.31 U2.32 U2.33 U2.34 U2.35 U2.36 U2.37 U2.38 U2.39 U3.19 U3.20 U3.21 U3.22 U3.23 U3.24 U3.25 U3.26 U3.27 U3.30 U3.31 U3.35 U3.36 U4.18 U4.19 U4.20 U4.21 U4.22 U4.23 U4.24 U4.25 U4.26 U4.28 U4.29 U4.30 U4.31 U4.32 U4.33 U4.34 U4.35 U4.36 U4.37 U4.38 U4.39 U5.8 U6.3 U7.3 U8.2 U8.3 U8.4 U8.5 U8.6 U8.7 U8.8 U8.9 U8.10 U8.11 U8.12 U8.13 U8.14 U8.15 | length 67
  Top Layer w0.25: C39.2@-116.1,112.7 -116.1,111.95 -115.1,110.95 v1(-115.1,110.9) ; U3.27@-114.5,104.3 U3.26@-114.5,103.65 U3.25@-114.5,103 ; U3.35@-114.5,109.5 U3.36@-114.5,110.05 ; U3.36@-114.5,110.15 -112.55,110.15 C21.2@-112.475,110.225 ; U3.19@-114.425,99.175 -114.475,99.175 -114.5,99.2 U3.20@-114.5,99.75 U3.21@-114.5,100.4 U3.22@-114.5,101.05 U3.23@-114.5,101.7 U3.24@-114.5,102.35 U3.25@-114.5,103 ; U3.30@-114.425,106.3 -114.45,106.3 -114.5,106.35 U3.31@-114.5,106.9 -114.462,106.862 -112.962,106.862 v1@-112.95,106.85 ; v1(-112.35,111.375) -112.35,110.325 C21.2@-112.25,110.225 ; C21.2@-112.25,110.125 -110.775,110.125 R15.2@-110.725,110.175 ; C35.1@-112.075,118.2 C34.1@-112.075,116.7 ; C32.1@-112.05,113.9 -112.075,113.925 C33.1@-112.075,115.3 C34.1@-112.075,116.7 ; C16.1@-111.925,103.425 C17.1@-110.575,103.425 C19.1@-107.475,103.425 ; C16.1@-111.925,103.475 -111.979,103.421 -112.979,103.421 -113.35,103.05 -114.45,103.05 U3.25@-114.5,103 ; v1@-110.8,117.325 -110.874,117.251 -110.874,116.876 -111.05,116.7 C34.1@-112.075,116.7 ; C47.2@-105.6,114.05 -104.825,114.05 -104.249,113.474 -104.249,113.349 v1(-104.2,113.3) ; v1(-105.5,117.75) U7.3@-104.45,117.75 ; v1@-101.45,106.075 -101.45,107.05 C43.2@-101.4,107.1 ; C248.1@-101.2,117.525 -101.2,119.025 R330.1@-101.2,119.125 -101.1,119.025 v1@-100.05,119.025 ; C247.1@-101.15,115.75 -101.2,115.7 R329.1@-101.2,114.35 -100.17,114.35 -100.07,114.25 v1(-100,114.25) ; v1(-100.72,111.65) -100.672,111.602 -100.672,110.975 -100.624,110.975 -100.449,110.8 U6.3@-100.3,110.8 ; v1(-100,119.025) -99.379,118.404 -97.604,118.404 C40.2@-97.4,118.2 ; C246.1@-97,110 C245.1@-97,108.5 R237.1@-97,107 -97,105.97 -96.98,105.95 v1@-96.95,105.95 ; R328.1@-97,111.8 -96.775,111.575 -96,111.575 v1@-95.925,111.65 ; R17.1@-91.8,99.4 -91.9,99.3 L2.1@-91.9,98.075 -91.887,98.088 -90.812,98.088 v1(-90.8,98.1) ; R17.1@-91.7,99.4 R17.1@-91.605,99.305 ; L3.1@-91.45,112.275 -91.45,113.45 R42.1@-91.3,113.6 -91.255,113.555 -90.55,113.555 v1(-90.046,113.051) ; v1(-90.046,114.051) -89.049,114.051 C26.1@-88.8,114.3 ; C28.2@-89.325,108.659 C28.2@-89.284,108.7 ; C15.2@-89.309,94.5 -89.059,94.25 v1(-88.254,94.25) ; C13.1@-88.475,100.05 -88.45,100.075 -88.45,101.425 v1@-88.475,101.45 ; R30.1@-85.25,114.325 -85.175,114.25 C27.1@-83.175,114.25 ; v1(-85.2,101.4) -85.2,100.225 -85.3,100.125 R10.1@-85.2,100.025 C14.1@-83.625,100.025 ; C11.2@-84.35,95.7 C11.2@-84.25,95.6 ; C24.2@-84.25,109.925 C24.2@-84.2,109.975 C24.2@-84.075,109.85 ; C14.1@-83.55,100.025 -83.475,99.95 -82.9,99.95 -82.55,99.6 -81.75,99.6 C12.2@-81.7,99.55 ; v1(-83.55,115.65) -83.55,114.625 C27.1@-83.175,114.25 ; C25.1@-81.75,114.25 C27.1@-83.175,114.25
  other v1: -86.1,94.2 -85.4,94.2 -84.7,94.2 -84.2,94.5 -86.5,94.7 -85.8,94.7 -85.15,94.7 -111.994,99.969 -113.048,100.002 -112.994,100.969 -111.994,100.969 -110.994,100.969 -88.425,101.45 -112.994,101.969 -111.994,101.969 -111.019,101.969 -109.994,101.969 -113.175,103.2 -96.95,105.85 -106,106 -105,106 -101.45,106 -112.95,106.825 -107,107 -106,107 -105,107 -108,108 -107,108 -106,108 -86.5,108.3 -85.9,108.3 -85.3,108.3 -84.7,108.3 -86.5,108.9 -85.9,108.9 -85.3,108.9 -108,110 -107.004,110.018 -114.4,110.9 -113.7,110.9 -108,111 -107,111 -95.9,111.575 -110,113 -109,113 -110,114 -109,114 -110,115 -109,115 -98,116 -97,116 -96,116 -84.046,116.051 -83.046,116.051 -99,117 -98,117 -97,117 -84.046,117.051 -83.046,117.051 -110.825,117.25 -97,120 -96,120 -117.1,121 -116.4,121 -115.7,121
SW_2: C44.2 C48.1 C57.2 C58.2 C59.1 C60.1 C61.2 C62.1 C63.1 C65.2 C66.2 C69.2 C70.1 C71.1 C72.1 C73.2 C77.1 C78.1 C79.1 C80.1 C85.2 C89.1 C91.2 C188.1 C240.2 C249.1 C250.1 D8.2 L4.1 L6.1 L7.1 R33.1 R34.1 R44.1 R49.2 R51.1 R52.1 R60.1 R331.1 R332.1 TP10.1 TP18.1 U9.18 U9.19 U9.20 U9.21 U9.22 U9.23 U9.24 U9.25 U9.26 U9.28 U9.29 U9.30 U9.31 U9.32 U9.33 U9.34 U9.35 U9.36 U9.37 U9.38 U9.39 U10.19 U10.20 U10.21 U10.22 U10.23 U10.24 U10.25 U10.26 U10.27 U10.30 U10.31 U10.35 U10.36 U11.18 U11.19 U11.20 U11.21 U11.22 U11.23 U11.24 U11.25 U11.26 U11.28 U11.29 U11.30 U11.31 U11.32 U11.33 U11.34 U11.35 U11.36 U11.37 U11.38 U11.39 U12.8 U13.3 U14.3 U15.2 U15.3 U15.4 U15.5 U15.6 U15.7 U15.8 U15.9 U15.10 U15.11 U15.12 U15.13 U15.14 U15.15 | length 93.2
  Top Layer w0.25: R34.1@-66.6,87.9 -66.5,88 C70.1@-66.5,95 ; C70.1@-66.5,95.05 R60.1@-62.725,95.05 ; C58.2@-65.475,109.375 C58.2@-65.5,109.4 C60.1@-63.8,109.4 -62.9,109.4 -62.7,109.2 R44.1@-62.3,109.2 ; v1(-64.75,114.3) -64.75,113.75 -64.5,113.5 C57.2@-63.75,113.5 ; D8.2@-64.25,116.137 -64.25,115.095 -64,114.845 C57.2@-64,113.75 ; C69.2@-64,99.5 v1(-64,100.5) ; v1@-63.8,87.4 -63.8,87.5 -63.3,88 U14.3@-63.1,88 ; R44.1@-62.279,109.021 -62.1,108.842 v1(-62.1,108.4) ; C44.2@-62.025,91.675 -62.025,92.675 v1@-61.9,92.8 ; v1(-61.5,101) -58.837,101 -58.837,100.071 C73.2@-58.691,99.925 ; R52.1@-61.5,101.8 R52.1@-61.3,102 ; C71.1@-59.6,95 -58.35,95 -56.75,96.6 L7.1@-56.4,96.6 ; v1@-59,116.25 -58.941,116.191 C61.2@-58.941,114.725 ; C61.2@-58.9,114.6 -58.431,114.131 -58.431,113.373 -56.775,111.717 -56.775,111.625 -56.575,111.425 L6.1@-56.1,111.425 -56.025,111.5 -55.25,111.5 -54.4,112.35 R51.1@-54.4,114.4 ; v1(-58.7,108.4) C59.1@-58.7,109.2 ; TP18.1@-58.5,104.5 -58.25,104.25 v1(-58.25,102.95) ; v1(-57.6,88.9) -57.551,88.949 -57.551,89.527 -57.404,89.674 -56.826,89.674 -56.675,89.825 -56.675,89.425 -56.975,89.125 -56.975,88.025 U10.36@-57.025,87.975 ; v1(-57.5,88) -57.05,88 U10.36@-57.025,87.975 ; R49.2@-57,91.7 -57.064,91.636 -57.691,91.636 -57.95,91.377 v1(-57.95,90.534) -57.95,90.475 -57.475,90 C66.2@-56.725,90 ; U10.35@-56.325,88 -56.35,87.975 U10.35@-56.375,87.975 U10.36@-57.025,87.975 ; R332.1@-55,105.3 C250.1@-53.9,105.3 C249.1@-52.4,105.3 R331.1@-50.9,105.3 -49.97,105.3 -49.87,105.4 v1(-49.8,105.4) ; v1(-54,101) -53.93,101 -53.629,101.301 -53.613,101.301 -53.613,101.962 -53.575,102 U13.3@-53.45,101.875 ; U10.31@-53.775,87.975 U10.30@-53.15,87.975 ; v1(-53.15,89.334) -53.138,89.321 -53.138,87.988 U10.30@-53.125,87.975 ; U10.30@-53.138,87.963 U10.30@-53.1,87.925 ; U10.27@-51.175,87.95 -51.15,87.975 U10.26@-50.525,87.975 U10.25@-49.875,87.975 ; C188.1@-50.45,94.65 -50.425,94.625 C63.1@-50.425,91.875 ; C62.1@-50.4,90.1 C63.1@-50.4,91.7 ; C62.1@-50.375,89.75 C62.1@-50.346,89.721 ; U10.25@-49.925,88.025 U10.25@-49.875,87.975 ; C91.2@-49.9,100.8 -49.75,100.95 v1(-49.75,101.75) ; U10.24@-49.225,88.575 -49.2,88.6 -49.2,89.35 -49.575,89.725 -50.125,89.725 C62.1@-50.4,90 -48.975,90 v1(-48.95,90.025) ; v1@-48.2,95 -47.225,95 C79.1@-47.05,95.175 ; v1@-48.125,96.7 -47.075,96.7 C80.1@-47.05,96.675 ; v1@-48.05,93.825 -47.25,93.825 C78.1@-47.1,93.675 ; C77.1@-47.1,92.275 C78.1@-47.1,93.6 ; U10.19@-45.925,87.975 U10.19@-45.975,87.975 U10.20@-46.625,87.975 U10.21@-47.275,87.975 U10.22@-47.925,87.975 U10.23@-48.575,87.975 U10.24@-49.225,87.975 U10.25@-49.875,87.975 ; v1@-44.3,98.8 C85.2@-43,98.8 ; U12.8@-43,91 -42.516,91 -42.299,90.784 -42.299,90.549 v1(-42.25,90.5) ; C85.2@-43,98.9 C240.2@-43,103.4
  Bottom Layer w0.25: U11.18@-64.035,110.475 U11.21@-62.085,110.475 ; v1(-62.1,108.4) -62.093,108.407 -62.093,110.468 U11.21@-62.085,110.475 ; U11.26@-58.835,110.475 U11.21@-62.085,110.475
  other v1: -45.45,87.3 -44.9,87.3 -44.3,87.3 -63.75,87.425 -61.975,87.475 -45.4,87.9 -44.8,87.9 -44.3,88.2 -45.2,88.5 -66.5,88.675 -61.725,88.95 -53.8,89.8 -47.7,89.8 -48.3,90.2 -61.975,90.396 -49.3,90.5 -48.7,90.8 -49.3,91.1 -66.5,91.593 -61.85,92.925 -66.45,93.525 -65.9,93.6 -48.175,93.8 -54,94 -48.2,94.95 -58.875,95 -48.175,96.725 -44.335,98.811 -63,100.5 -62,100.5 -62.5,101 -44,101 -42.4,101.05 -44.5,101.8 -43.9,101.8 -43.3,101.8 -42.7,101.8 -44.5,104.4 -43.9,104.4 -43.3,104.4 -42.7,104.4 -54.5,112.5 -62.55,114.325 -61.95,114.325 -64.05,114.825 -63.45,114.825 -62.85,114.825 -62.25,114.825 -59,116.3
SW_mid: TP1.1 TP5.1 U4.2 U4.3 U4.4 U4.5 U4.6 U4.7 U4.8 U4.9 U4.10 U4.11 U4.12 U4.13 U4.14 U4.15 U11.2 U11.3 U11.4 U11.5 U11.6 U11.7 U11.8 U11.9 U11.10 U11.11 U11.12 U11.13 U11.14 U11.15
  other v1: -67.25,104 -81,104.25 -81,105 -67.25,105 -81,105.75 -67.25,106
TEMP_ACDC: R222.2 U23.5 | length 66.6
  Top Layer w0.25: v1(-183.8,97.4) -183.751,97.351 -183.751,97.081 R222.2@-183.75,95.65 ; v1(-139.7,99.3) -139.688,99.288 -138.112,99.288 v1@-138.1,99.3 ; U23.5@-126.825,92.1 v1(-125.6,92.1)
  Layer 2 w0.25: v1(-183.8,97.4) -183.2,98 -172.5,98 -171.397,99.103 -165.405,99.103 -164.773,98.471 -158.781,98.471 -158.598,98.654 -146.365,98.654 -145.961,98.25 -140.75,98.25 v1(-139.7,99.3) ; v1@-138,99.3 -134.452,99.3 -131.827,96.675 v1(-128.675,96.675)
  Bottom Layer w0.25: v1@-128.716,96.685 -128.716,95.216 v1(-125.6,92.1)
  other v1: -138.075,99.275
TEMP_AMB_sense: C10.1 R5.1 R6.1 R182.2 | length 59.5
  Top Layer w0.25: R6.1@-240.5,112.73 -240.48,112.75 -239.396,112.75 -239.25,112.604 -239.25,112.55 -238.75,112.05 -230.55,112.05 -227.436,108.936 -227.436,108.728 -227.575,108.589 -227.575,102.661 -226.65,101.736 -226.65,96.598 -227.029,96.219 -227.029,95.781 -225.25,94.002 -225.25,79.5 -224,78.25 -220.3,78.25 -215.375,73.325 R182.2@-215.375,73.3 ; R5.1@-238,112.025 C10.1@-238,113.625
TEMP_Batt_H1_Buff: C177.2 J12.4 U24.2 | length 41.2
  Top Layer w0.25: U24.2@-126.525,81.925 -125.45,81.925 -124.975,81.45 C177.2@-124.45,81.45
  Layer 2 w0.25: v1@-125.25,81.75 -125.175,81.675 -123.727,81.675 -114.171,72.119 -114.171,62.283 -122.669,53.785 -123.45,53.785 J12.4@-124.285,54.62
  other v1: -125.275,81.675
TEMP_Batt_H2_Buff: C179.2 J12.12 U24.15 | length 45
  Top Layer w0.25: C179.2@-134.925,81.575 -134.15,81.575 -133.8,81.925 -132.992,81.925 -132.975,81.942 U24.15@-132.975,81.95
  Layer 2 w0.25: v1(-133.95,81.825) -138.225,81.825 -139.096,80.954 -139.096,54.096 -138.25,53.25 -130.735,53.25 -129.5,54.485 J12.12@-129.5,54.575
TEMP_Batt_L1_Buff: C178.2 J12.2 U24.1 | length 36.2
  Top Layer w0.25: U24.1@-126.525,81.275 -126.525,79.975 C178.2@-126.45,79.9
  Layer 2 w0.25: v1(-126.5,80.575) -126.048,80.575 -122.894,77.421 -122.798,77.421 -114.571,69.194 -114.571,62.855 -122.806,54.62 J12.2@-123.015,54.62
TEMP_Batt_L2_Buff: C180.2 J12.10 U24.14 | length 49.6
  Top Layer w0.25: C180.2@-134.925,83.175 -134.125,83.175 -133.5,82.55 -132.45,82.55 U24.14@-132.425,82.575
  Layer 2 w0.25: v1@-133.925,83.075 -137.7,83.075 -139.75,81.025 -139.75,53.85 -138.575,52.675 -130.04,52.675 J12.10@-128.095,54.62
  other v1: -133.9,82.95
TEMP_Boost1_Buff: C174.2 J12.8 U24.4 | length 49
  Top Layer w0.25: U24.4@-126.525,83.225 -126.487,83.263 -125.637,83.263 -125.275,83.625 -125.275,84.325 -124.954,84.646 -124.479,84.646 C174.2@-124.45,84.675
  Layer 2 w0.25: J12.8@-126.825,54.62 -125.19,52.985 -120.815,52.985 -113.221,60.579 -113.221,72.3 -124.421,83.5 -125.275,83.5 v1@-125.325,83.55
  other v1: -125.375,83.5
TEMP_Boost2_Buff: C175.2 J12.6 U24.3 | length 44.8
  Top Layer w0.25: U24.3@-126.525,82.575 v1@-125.35,82.575 ; v1(-125.225,82.75) -125.175,82.75 -125,82.925 -124.575,82.925 -124.525,82.975 C175.2@-124.525,83.025
  Layer 2 w0.25: J12.6@-125.555,54.62 -124.32,53.385 -121.165,53.385 -113.621,60.929 -113.621,72.135 -124.236,82.75 v1(-125.225,82.75)
TEMP_DCDC: R233.1 U24.5 | length 59.2
  Top Layer w0.25: R233.1@-177.86,77.251 -177.811,77.3 v1@-176.8,77.3 ; v1(-164.975,79.075) -164.926,79.124 -164.926,79.774 v1(-164.4,80.3) ; v1@-134.6,77.9 -131.3,77.9 -130.4,78.8 -130.4,80.532 -127.207,83.725 -127.204,83.725 -127.054,83.875 U24.5@-126.525,83.875
  Layer 2 w0.25: v1(-176.775,77.375) -176.246,76.846 -171.193,76.846 -171.093,76.946 -170.655,76.946 -170.555,76.846 -167.154,76.846 v1@-164.9,79.1 ; v1(-164.4,80.3) -163.655,81.045 -160.005,81.045 -159.25,81.8 v1(-155.6,81.8)
  Bottom Layer w0.25: v1(-155.6,81.8) -147.385,81.8 -143.46,77.875 v1(-134.675,77.875)
TEMP_MUX_A: R216.2 U23.11 U24.11 | length 69.2
  Top Layer w0.25: R216.2@-187,92.1 v1(-187,92.9) ; v1@-133.9,92.8 -133.85,92.75 U23.11@-132.725,92.75 ; v1(-133.78,84.646) -133.711,84.646 -133.59,84.525 U24.11@-132.425,84.525
  Layer 2 w0.25: v1(-175.125,93.55) -175.12,93.555 -168.585,93.555 -167.73,92.7 -163.048,92.7 -162.748,93 -138.19,93 v1(-136.871,91.681) ; v1(-134,92.7) -133.3,92.7 -131,90.4 -131,87.2 -132.252,85.948 -132.479,85.948 v1(-133.78,84.646)
  Bottom Layer w0.25: v1(-187,92.9) -186.3,93.6 v1@-175.1,93.6 ; v1(-136.871,91.681) -135.852,92.7 v1(-134,92.7)
TEMP_MUX_B: R218.2 U23.10 U24.10 | length 74.5
  Top Layer w0.25: v1(-186.1,97.3) -186.1,97.23 -185.9,97.03 -185.9,95.6 R218.2@-185.875,95.575 ; v1(-171.925,96.75) -170.675,98 -168.3,98 -167.3,99 -163.9,99 -162.025,97.125 -159.225,97.125 v1@-158.2,96.1 ; v1(-135,85.2) -134.975,85.175 U24.10@-132.425,85.175 ; v1@-134,93.5 -133.9,93.4 U23.10@-132.725,93.4
  Layer 2 w0.25: v1(-158.225,96.05) -149.573,96.05 -148.519,94.996 -134.096,94.996 -133.471,94.371 -133.471,93.881 -133.952,93.4 v1(-134,93.4)
  Bottom Layer w0.25: v1(-186.1,97.3) -185.55,96.75 -171.855,96.75 v1@-171.806,96.799 ; v1(-135,85.2) -137.4,87.6 -137.4,91.9 -135.9,93.4 v1(-134,93.4)
TEMP_MUX_C: R220.2 U23.9 U24.9 | length 65
  Top Layer w0.25: R220.2@-184.7,91.8 v1(-184.7,92.9) ; v1@-134.1,94.1 -134.075,94.075 -132.75,94.075 U23.9@-132.725,94.05 ; v1(-133.7,85.8) -133.687,85.813 -132.438,85.813 U24.9@-132.425,85.825
  Layer 2 w0.25: v1@-184.8,93 -183.55,94.25 -170.398,94.25 -170.149,94.001 -165.843,94.001 -165.594,94.25 -139.398,94.25 -138.819,93.671 -136.781,93.671 -136.352,94.1 v1(-134,94.1) ; v1@-134.048,94.1 -135.1,93.048 -135.1,87.2 v1(-133.7,85.8)
TEMP_S1: C167.2 R26.1 U23.4 | length 26.7
  Top Layer w0.25: R26.1@-127.35,115.075 -127.3,115.025 v1(-127.3,113.8) ; U23.4@-126.3,91.45 -125.45,91.45 -125.049,91.851 -125.049,92.451 v1(-125,92.5) -124.025,92.5 C167.2@-123.95,92.575
  Layer 2 w0.25: v1(-127.3,103.5) -126.3,102.5 -126.3,95.073 -126.296,95.069 -126.296,94.631 -126.3,94.627 -126.3,93.8 v1(-125,92.5)
  Bottom Layer w0.25: v1(-127.3,103.5) v1(-127.3,113.8)
TEMP_S1_init: R27.2 U2.49 | length 2.9
  Top Layer w0.25: R27.2@-86.85,98.425 -86.75,98.325 -86.75,97.896 -86.583,97.729 -86.079,97.729 -85.6,97.25 v1@-85.575,97.25
  Bottom Layer w0.25: U2.49@-85.575,96.325 -85.563,96.337 -85.563,97.213 v1(-85.575,97.225)
TEMP_S2: C168.2 R39.2 U23.3 | length 23.3
  Top Layer w0.25: R39.2@-141.046,89.04 -140.905,88.9 v1@-139.9,88.9 ; v1(-135.725,86.85) -133.707,86.85 -133.353,86.496 -130.133,86.496 -129.5,87.129 -126.174,87.129 -126.144,87.099 v1@-126.001,87.099 ; U23.3@-126.425,90.8 -124.15,90.8 C168.2@-124,90.95
  Layer 2 w0.25: v1(-140.025,88.85) -137.975,86.8 v1@-135.7,86.8 ; v1@-126,87 -125.025,87.975 v1(-125.025,90.85)
  other v1: -126.025,87.05
TEMP_S2_init: C52.2 R37.1 R38.1 | length 54.3
  Top Layer w0.25: R38.1@-141.046,85.23 -141.046,83.646 C52.2@-141.025,83.625 ; v1(-133.2,97.3) -133.175,97.325 -124.65,97.325 v1(-124.625,97.35) ; R37.1@-101.15,100.1 -101.1,100.15 v1(-101.1,101.1)
  Layer 2 w0.25: v1@-124.617,97.383 -124.617,97.369 -124.094,96.846 -124.08,96.846 -123.234,96 -112.515,96 -112.219,95.704 -111.296,95.704 -106.3,100.7 -104.927,100.7 -104.427,100.2 -102,100.2 v1(-101.1,101.1)
  Bottom Layer w0.25: v1(-141.025,84.35) -139.346,86.029 -139.346,90.52 -136.471,93.395 -136.471,94.077 -133.248,97.3 v1(-133.2,97.3)
TEMP_S3: C170.2 R61.1 U23.2 | length 140.7
  Top Layer w0.25: U23.2@-126.825,90.15 -125.427,90.15 ; -125.4,90.15 -124.675,89.425 C170.2@-124.05,89.425 ; C170.2@-123.9,89.375 -123.9,88.575 -123.2,87.875 -121.675,87.875 -120.2,86.4 -120.2,82.05 -122.675,79.575 -122.675,78.05 v1@-122.725,78 ; R61.1@-34.25,85.2 -34.1,85.05 -34.1,80.025 v1@-34.075,80
  Bottom Layer w0.25: v1(-122.675,77.95) -122.675,76.775 -118.43,72.53 -118.42,72.53 -118.11,72.22 -118.11,72.21 -108.1,62.2 -100.8,62.2 -90.3,51.7 -52.8,51.7 -34.1,70.4 v1(-34.1,80)
TEMP_S3_init: R62.2 U9.49 | length 4
  Top Layer w0.25: v1@-62.659,112.225 -62.675,112.225 -62.146,111.696 -60.546,111.696 -60.4,111.55 R62.2@-60.4,111.2
  Bottom Layer w0.25: U9.49@-62.735,113.275 -62.705,113.245 -62.705,112.255 v1@-62.675,112.225
  other v1: -62.675,112.325
TEMP_S4: C171.2 R73.2 U23.1 | length 35
  Top Layer w0.25: v1(-152.7,94.9) -152.7,93.825 R73.2@-152.675,93.8 ; U23.1@-126.825,89.5 -126.792,89.5 -126.7,89.408 C171.2@-126.7,88.275 ; C171.2@-126.75,88.05 -126.7,88.1 v1@-125.7,88.1
  Layer 2 w0.25: v1@-147.8,95.7 -146.4,97.1 -134.675,97.1 v1(-125.725,88.15)
  Bottom Layer w0.25: v1(-152.7,94.9) -152.297,95.303 -148.242,95.303 -147.9,95.645 v1@-147.9,95.7
  other v1: -147.825,95.65
TEMP_S4_init: C98.2 R71.1 R72.1 | length 196.3
  Top Layer w0.25: R72.1@-157.175,95.575 -157.05,95.7 C98.2@-157.05,97 -156.95,97.1 v1(-156.95,98.125) ; v1(-148.75,86.375) -148.725,86.4 -148.725,96.075 v1(-148.7,96.1) ; v1(-46.925,108.225) -46.925,109.05 R71.1@-46.9,109.075
  Bottom Layer w0.25: v1(-156.95,98.125) -150.773,98.125 -148.748,96.1 v1(-148.7,96.1) ; v1@-148.725,86.375 -148.725,85.425 -141.725,78.425 -132.773,78.425 -132.669,78.321 -132.231,78.321 -132.127,78.425 -122.948,78.425 -122.894,78.479 -122.456,78.479 -122.402,78.425 -120.825,78.425 -106.9,64.5 -98.2,64.5 -90.7,57 -56,57 -37.6,75.4 -37.6,81.15 -36.5,82.25 -36.5,104.5 -41.2,109.2 -45.95,109.2 v1(-46.925,108.225)
TEMP_S5: C172.2 R24.1 U23.15 | length 38.9
  Top Layer w0.25: v1(-135.5,96.1) -135.57,96.1 -135.699,96.229 -136.871,96.229 -137.529,95.571 -137.529,89.029 -137.1,88.6 -135.4,88.6 -135.075,88.925 C172.2@-135.075,89.725 -134.225,89.725 -133.8,90.15 -133.25,90.15 U23.15@-133.2,90.2 ; v1@-128.3,116.6 -127.45,116.6 R24.1@-127.325,116.475
  Layer 2 w0.25: v1@-130.6,109.1 -130.6,114.3 v1(-128.4,116.5)
  Bottom Layer w0.25: v1(-135.5,96.1) -131.595,100.005 -131.595,108.08 -130.7,108.975 v1@-130.7,109.1
  other v1: -130.625,109.05
TEMP_S5_init: R25.2 U4.49 | length 3.1
  Top Layer w0.25: R25.2@-87,112.7 -86.975,112.675 -86.35,112.675 -86.162,112.487 -86.162,111.888 -85.722,111.447 -85.722,111.353 v1@-85.725,111.35
  Bottom Layer w0.25: v1(-85.65,111.35) -85.601,111.301 -85.601,110.675 -85.526,110.6 U4.49@-85.475,110.6
TEMP_S6: C173.2 R58.1 U23.14 | length 141.4
  Top Layer w0.25: C173.2@-135.7,93 -135.6,93.1 -135,93.1 -134.6,92.7 -134.6,91.5 -133.9,90.8 v1@-133.9,90.7 ; v1@-133.9,90.85 -133.2,90.85 U23.14@-133.15,90.9 ; v1(-127.65,76.85) -127.625,76.825 -121.225,76.825 v1(-121.2,76.8) ; R58.1@-35.05,81.925 -34.95,81.825 v1(-34.95,80.6)
  Layer 2 w0.25: v1@-127.95,79.1 -127.95,77.15 v1(-127.65,76.85)
  Bottom Layer w0.25: v1(-134,90.85) -127.95,84.8 v1@-127.95,79.05 ; v1(-121.2,76.8) -121.2,76.3 -114.525,69.625 -107.9,63 -100.1,63 -90.5,53.4 -53.6,53.4 -34.95,72.05 v1(-34.95,80.6)
  other v1: -127.975,79.075
TEMP_S6_init: R59.2 U11.49 | length 3.2
  Top Layer w0.25: v1(-62.5,97.85) -62.5,97.78 -62.15,97.43 -62.15,96.725 -62,96.575 -61.525,96.575 R59.2@-61.475,96.525
  Bottom Layer w0.25: U11.49@-62.775,98.875 -62.75,98.85 -62.75,98.17 -62.5,97.92 v1(-62.5,97.85)
VAC_L: K1.3 L11.3 R75.1 R111.1 | length 2.4
  Top Layer w0.25: R111.1@-210,127.1 -210,128.75 -209.5,129.25
VAC_N: K2.1 L11.2 R114.1 R122.1 | length 29.2
  Top Layer w0.25: R122.1@-219.75,129.1 v1(-219.75,130)
  Layer 2 w0.25: L11.2@-221.4,154.3 -215.75,148.65 -215.75,139.75 -219.75,135.75 v1(-219.75,130)
VAC_sense: C132.2 R120.2 R178.1 | length 26
  Top Layer w0.25: R120.2@-218.2,112 -218.15,111.95 -217.45,111.95 -216.474,110.974 v1(-216.474,100.417) ; R178.1@-211.975,91.975 v1@-211.975,92.875 ; C132.2@-209.84,91.985 C132.2@-209.8,92.025 v1@-209.8,92.925
  Layer 2 w0.25: v1(-216.474,100.417) -216.474,99.974 -212,95.5 v1(-212,93.05)
  Bottom Layer w0.25: v1(-212,93.05) -209.85,93.05 v1@-209.775,92.975
  other v1: -209.8,93.05
VAC_SW+: C102.1 C104.2 L10.2 R116.1 U16.1 | length 11.5
  Top Layer w0.5: C104.2@-180.2,129.05 -175.55,129.05 -175.25,128.75 -175.25,128 -175.15,127.9 R116.1@-175.15,122.4
  other v1: -182,128 -181,128 -179,128 -178,128 -156,128 -155,128 -154,128 -182,129 -179,129 -156,129 -155,129 -154,129 -177.875,129.05 -182,130 -181,130 -179,130 -178,130 -156,130 -155,130 -154,130 -182,131 -181,131 -180,131 -179,131 -178,131 -156,131 -155,131 -180,132 -179,132 -178,132 -156,132 -155,132 -180,133 -179,133 -178,133 -156,133 -155,133 -156,134 -155,134
VDC_sense: C133.2 R174.2 U32.1 U32.2 | length 222.8
  Top Layer w0.25: v1@-220.575,93.075 -220.565,93.065 C133.2@-220.565,91.939 -218.839,91.939 R174.2@-218.775,91.875 ; v1(-196.066,103.066) -191.184,103.066 -190.25,104 -188.75,104 -188,103.25 -173.5,103.25 v1(-166,110.75) ; v1(-137.5,114.25) -133.4,110.15 v1@-133.4,109.8 ; v1(-92.325,17.225) -89.775,17.225 -89,18 -89,19.347 U32.1@-88.847,19.5 ; U32.1@-88.675,19.495 U32.2@-88.675,20.765
  Layer 2 w0.25: v1(-220.55,93.1) -220.55,94.305 -221.404,95.159 -221.404,96.996 -216.15,102.25 -204.875,102.25 -204.059,103.066 v1(-196.066,103.066) ; v1(-166,110.75) -161.275,115.475 -144.455,115.475 -142.88,113.9 -138.652,113.9 -138.302,114.25 v1(-137.5,114.25) ; v1@-133.301,109.683 -127.975,104.357 v1(-127.975,98.075) ; v1(-125,94.8) -122.3,92.1 -122.3,91.115 -122.2,91.015 -122.2,82.6 -112.4,72.8 -112.4,65 v1(-99.8,52.4)
  Bottom Layer w0.25: v1@-128,98.1 -128,97.8 v1(-125,94.8) ; v1(-99.8,52.4) -98.9,52.4 -94.6,48.1 -94.6,26.1 -92.325,23.825 v1(-92.325,17.225)
  other v1: -133.359,109.675
VIN_PWR_CAN: J15.4
Vinv_sense: C134.2 R121.2 R176.1 | length 23.9
  Top Layer w0.25: R121.2@-226.25,102.7 -226.25,101.75 -224.75,100.25 -217.75,100.25 -217,99.5 -215.25,99.5 -213.75,101 -213.152,101 -210.045,97.893 -210.045,95.7 ; R176.1@-210.8,95.7 R176.1@-210.683,95.7 ; R176.1@-210.683,95.817 -210.566,95.7 -210.045,95.7 ; -209.67,95.67 C134.2@-209.099,95.67 ; -209.67,95.7 -210.045,95.7
VP_CAN: C198.2 C205.1 C207.1 C210.2 C211.2 C212.1 C213.1 J16.2 U30.12 U30.13 U30.20 | length 55.1
  Top Layer w0.25: -259.7,104.075 -259.706,104.081 ; -259.652,104.081 -259.652,103.077 -259.175,102.6 -255.225,102.6 -254.523,103.302 U30.13@-250.156,103.302 v1(-250.156,103.937) U30.12@-250.156,104.572 ; C211.2@-259.506,109.312 -259.519,109.325 -260.075,109.325 -260.45,108.95 -260.45,104.45 -260.081,104.081 -259.706,104.081 ; C207.1@-257.982,93.65 -256.725,93.65 -256.352,94.023 C198.2@-255.696,94.023 ; C213.1@-257.45,104.1 -257.465,104.085 -259.701,104.085 -259.706,104.081 ; C213.1@-256.723,104.183 -255.548,104.183 -255.149,104.582 -254.718,104.582 C210.2@-254.7,104.6 ; C198.2@-255.696,94.05 C205.1@-252.425,94.05 ; C210.2@-254.437,104.572 -252.569,104.572 -252.525,104.528 C212.1@-252.525,104.475 ; C205.1@-252.394,93.996 -251.754,93.996 -251.4,94.35 -251.075,94.35 U30.20@-251,94.425 ; J16.2@-251.33,83.5 -251.062,83.768 -251.062,87.738 -250.2,88.6 -250.2,92.75 U30.20@-250.2,94.4
  Layer 2 w0.25: v1(-250.25,92.75) -250.25,92.82 -250.156,92.914 v1(-250.156,103.937)
VP_RS485: C223.2 C224.1 C225.1 C226.2 C227.1 C228.1 U31.12 U31.16 | length 31.5
  Top Layer w0.25: C225.1@-256.9,60.6 v1(-258.5,60.6) -258.5,62.25 -260.5,64.25 -260.5,66.5 -258.497,68.503 -257.109,68.503 C228.1@-256.719,68.893 -256.526,68.7 -255.6,68.7 -254.7,67.8 -252.17,67.8 C227.1@-252.136,67.834 ; C225.1@-256.873,60.473 C223.2@-254.7,60.473 C224.1@-252.227,60.473 ; C224.1@-252.1,60.5 -252.1,60.492 -251.925,60.317 v1(-251.174,60.317) ; v1@-251.125,60.2 U31.16@-250.5,60.2 ; v1@-251.071,65.329 U31.12@-249.62,65.329
  Bottom Layer w0.25: v1@-258.619,60.551 -258.5,60.67 v1@-258.5,60.7 ; v1(-251.174,60.317) -251.629,60.772 -251.629,64.862 v1(-251.174,65.317)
